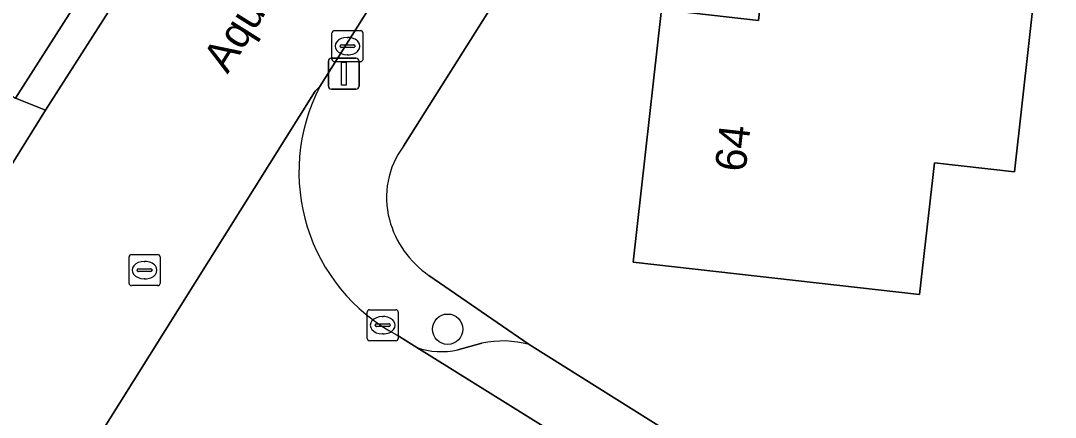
# Model space of a CAD drawing. Extents: x 162396 to 163643, y 386452 to 387406.
# Drawn here: x 162948.05 to 162981.44, y 387033.61 to 387046.39 of the extents above; entities that cross this region are included whole.
import ezdxf

# ---------------------------------------------------------------- set-up
doc = ezdxf.new("R2010")
doc.units = 0
for name, color, linetype in [('IMGEO_Boom', 7, 'Continuous'), ('IMGEO_Erf', 7, 'Continuous'), ('IMGEO_Groenvoorziening', 7, 'Continuous'), ('IMGEO_Kolk', 7, 'Continuous'), ('IMGEO_Lichtmast', 7, 'Continuous'), ('IMGEO_Openbare_ruimte_label', 7, 'Continuous'), ('IMGEO_Pand', 7, 'Continuous'), ('IMGEO_Pand_nummerreeks', 7, 'Continuous'), ('IMGEO_Parkeervlak_open', 7, 'Continuous'), ('IMGEO_Rijbaan_lokaal_open', 7, 'Continuous'), ('IMGEO_Rioolput', 7, 'Continuous'), ('IMGEO_Voetpad_open', 7, 'Continuous')]:
    doc.layers.add(name, color=color, linetype=linetype)

msp = doc.modelspace()

# ---------------------------------------------------------------- linework, layer by layer
at = {"layer": 'IMGEO_Boom'}
msp.add_circle((162961.83, 387036.448), 0.489, dxfattribs=at)
at = {"layer": 'IMGEO_Erf'}
for points in [[(162979.934, 387072.163), (162977.128, 387068.53), (162974.731, 387065.026), (162960.405, 387042.352)], [(162961.225, 387038.18), (162964.459, 387035.953), (162990.052, 387019.93), (162992.795, 387018.215), (163000, 387017.439), (163002.724, 387017.146), (163002.153, 387014.133), (163000, 387002.568), (162999.522, 387000), (162999.273, 386998.733), (162983.452, 386917.174), (162983.338, 386916.58), (162981.778, 386908.453)]]:
    msp.add_lwpolyline(points, dxfattribs=at)
msp.add_lwpolyline([(162980.122, 387041.524), (162977.543, 387041.815), (162977.063, 387037.568), (162967.816, 387038.612), (162968.734, 387046.749), (162971.862, 387046.396), (162972.389, 387051.073), (162981.089, 387050.091)], close=True, dxfattribs=at)
for centre, radius, start, end in [((162962.615, 387040.699), 2.76, 143.2137, 195.0422), ((162962.992, 387040.782), 3.145, 194.7138, 235.8186)]:
    msp.add_arc(centre, radius, start, end, dxfattribs=at)
at = {"layer": 'IMGEO_Groenvoorziening'}
msp.add_lwpolyline([(162964.245, 387069.484), (162941.168, 387071.891), (162939.105, 387055.217), (162936.596, 387055.509), (162935.833, 387055.438), (162935.116, 387055.166), (162934.413, 387053.638), (162934.581, 387052.537), (162935.398, 387051.666), (162947.885, 387043.899)], close=True, dxfattribs=at)
at = {"layer": 'IMGEO_Kolk'}
for p, q in [((162958.171, 387046.07), (162959.023, 387046.07)), ((162958.096, 387045.144), (162958.096, 387045.996)), ((162958.584, 387045.85), (162958.609, 387045.85)), ((162959.097, 387045.996), (162959.097, 387045.144)), ((162958.355, 387045.564), (162958.355, 387045.576)), ((162958.793, 387045.527), (162958.395, 387045.527)), ((162958.398, 387045.613), (162958.796, 387045.613)), ((162958.839, 387045.576), (162958.839, 387045.564)), ((162959.023, 387045.07), (162958.171, 387045.07)), ((162958.607, 387045.29), (162958.582, 387045.29)), ((162959.308, 387037.076), (162960.16, 387037.076)), ((162959.233, 387036.15), (162959.233, 387037.002)), ((162959.721, 387036.856), (162959.746, 387036.856)), ((162960.234, 387037.002), (162960.234, 387036.15)), ((162959.492, 387036.57), (162959.492, 387036.582)), ((162959.93, 387036.533), (162959.532, 387036.533)), ((162959.535, 387036.619), (162959.933, 387036.619)), ((162959.976, 387036.582), (162959.976, 387036.57)), ((162960.16, 387036.076), (162959.308, 387036.076)), ((162959.744, 387036.296), (162959.719, 387036.296))]:
    msp.add_line(p, q, dxfattribs=at)
for points in [[(162958.171, 387046.07), (162959.023, 387046.07)], [(162958.096, 387045.144), (162958.096, 387045.996)], [(162959.097, 387045.996), (162959.097, 387045.144)], [(162959.023, 387045.07), (162958.171, 387045.07)], [(162959.308, 387037.076), (162960.16, 387037.076)], [(162959.233, 387036.15), (162959.233, 387037.002)], [(162960.234, 387037.002), (162960.234, 387036.15)], [(162960.16, 387036.076), (162959.308, 387036.076)]]:
    msp.add_lwpolyline(points, dxfattribs=at)
for centre, radius, start, end in [((162958.173, 387045.994), 0.0765, 91.552, 178.448), ((162958.173, 387045.994), 0.0765, 91.552, 178.448), ((162959.021, 387045.994), 0.0765, 1.552, 88.448), ((162959.021, 387045.994), 0.0765, 1.552, 88.448), ((162958.395, 387045.573), 0.0403, 85.8775, 175.7526), ((162958.392, 387045.563), 0.0366, 178.938, 274.7102), ((162958.796, 387045.57), 0.043, 264.8664, 352.4533), ((162958.8, 387045.575), 0.0386, 1.7309, 96.639), ((162958.173, 387045.146), 0.0765, 181.552, 268.448), ((162958.173, 387045.146), 0.0765, 181.552, 268.448), ((162959.021, 387045.146), 0.0765, 271.552, 358.448), ((162959.021, 387045.146), 0.0765, 271.552, 358.448), ((162959.31, 387037), 0.0765, 91.552, 178.448), ((162959.31, 387037), 0.0765, 91.552, 178.448), ((162960.158, 387037), 0.0765, 1.552, 88.448), ((162960.158, 387037), 0.0765, 1.552, 88.448), ((162959.532, 387036.579), 0.0403, 85.8775, 175.7526), ((162959.529, 387036.569), 0.0366, 178.938, 274.7102), ((162959.933, 387036.576), 0.043, 264.8664, 352.4533), ((162959.937, 387036.581), 0.0386, 1.7309, 96.639), ((162959.31, 387036.152), 0.0765, 181.552, 268.448), ((162959.31, 387036.152), 0.0765, 181.552, 268.448), ((162960.158, 387036.152), 0.0765, 271.552, 358.448), ((162960.158, 387036.152), 0.0765, 271.552, 358.448)]:
    msp.add_arc(centre, radius, start, end, dxfattribs=at)
for centre, major_axis, ratio, start_param, end_param in [((162958.583, 387045.57), (-0.387, 0.002), 0.722429, 4.712389, 7.853982), ((162958.608, 387045.57), (-0.39, 0.002), 0.717154, 1.570796, 4.712389), ((162959.72, 387036.576), (-0.387, 0.002), 0.722429, 4.712389, 7.853982), ((162959.745, 387036.576), (-0.39, 0.002), 0.717154, 1.570796, 4.712389)]:
    msp.add_ellipse(centre, major_axis=major_axis, ratio=ratio, start_param=start_param, end_param=end_param, dxfattribs=at)
at = {"layer": 'IMGEO_Lichtmast'}
for p, q in [((162957.981, 387044.284), (162957.981, 387045.084)), ((162957.981, 387045.084), (162957.981, 387044.284)), ((162958.081, 387045.184), (162958.871, 387045.184)), ((162958.871, 387045.184), (162958.081, 387045.184)), ((162958.971, 387045.084), (162958.971, 387044.284)), ((162958.971, 387044.284), (162958.971, 387045.084)), ((162958.871, 387044.184), (162958.081, 387044.184)), ((162958.081, 387044.184), (162958.871, 387044.184))]:
    msp.add_line(p, q, dxfattribs=at)
msp.add_lwpolyline([(162958.401, 387045.059), (162958.551, 387045.059), (162958.551, 387044.309), (162958.401, 387044.309), (162958.401, 387045.059)], dxfattribs=at)
for centre, start, end in [((162958.081, 387045.084), 90, 180), ((162958.081, 387045.084), 90, 180), ((162958.871, 387045.084), 0, 90), ((162958.871, 387045.084), 360, 90), ((162958.081, 387044.284), 180, 270), ((162958.081, 387044.284), 180, 270), ((162958.871, 387044.284), 270, 0), ((162958.871, 387044.284), 270, 0)]:
    msp.add_arc(centre, 0.1, start, end, dxfattribs=at)
at = {"layer": 'IMGEO_Pand'}
msp.add_lwpolyline([(162977.543, 387041.815), (162980.122, 387041.524), (162981.089, 387050.091), (162972.389, 387051.073), (162971.862, 387046.396), (162968.734, 387046.749), (162967.816, 387038.612), (162977.063, 387037.568)], close=True, dxfattribs=at)
at = {"layer": 'IMGEO_Parkeervlak_open'}
for points in [[(162960.832, 387035.859), (162977.884, 387025.258), (162991.899, 387016.536)], [(162962.937, 387035.997), (162962.161, 387035.785)], [(162991.074, 387017.691), (162990.052, 387019.93), (162964.459, 387035.953)]]:
    msp.add_lwpolyline(points, dxfattribs=at)
for centre, radius, start, end in [((162963.609, 387032.908), 3.161, 74.4079, 102.2803), ((162961.626, 387038.149), 2.424, 250.8758, 282.7502)]:
    msp.add_arc(centre, radius, start, end, dxfattribs=at)
at = {"layer": 'IMGEO_Rijbaan_lokaal_open'}
for points in [[(162966.768, 387071.483), (162948.849, 387043.507), (162945.907, 387038.803), (162941.229, 387031.323), (162938.465, 387026.904), (162937.436, 387025.258), (162921.686, 387000.002), (162915.342, 386989.987), (162914.431, 386990.593), (162914.143, 386990.14), (162911.404, 386985.942), (162911.138, 386985.441), (162912.089, 386984.831), (162909.331, 386979.699), (162906.632, 386973.865), (162905.275, 386970.114), (162896.686, 386945.321)], [(162928.216, 387071.142), (162925.71, 387048.745), (162929.833, 387048.448), (162929.843, 387048.447), (162930.466, 387048.352), (162931.078, 387048.201), (162931.674, 387047.997), (162932.25, 387047.739), (162932.8, 387047.432), (162945.216, 387039.485), (162945.907, 387038.803), (162948.849, 387043.507), (162947.885, 387043.899)], [(162893.927, 386924.59), (162901.627, 386939.333), (162906.38, 386952.275), (162909.185, 386960.036), (162912.927, 386970.387), (162914.676, 386974.714), (162915.597, 386976.559), (162916.277, 386977.92), (162917.178, 386979.724), (162920.646, 386985.26), (162923.023, 386989.056), (162927.543, 386996.272), (162929.878, 387000), (162929.936, 387000.092), (162941.722, 387018.853), (162943.715, 387022.032), (162945.076, 387024.193), (162948.049, 387028.821), (162949.072, 387030.463), (162949.283, 387030.941), (162957.556, 387044.115), (162957.708, 387044.272), (162960.889, 387049.333)], [(162957.708, 387044.272), (162957.556, 387044.115), (162949.283, 387030.941), (162949.072, 387030.463)], [(162993.578, 387015.491), (162991.899, 387016.536), (162977.884, 387025.258), (162960.832, 387035.859), (162960.197, 387036.254)]]:
    msp.add_lwpolyline(points, dxfattribs=at)
msp.add_arc((162962.984, 387041.515), 5.953, 152.4074, 242.0841, dxfattribs=at)
at = {"layer": 'IMGEO_Rioolput'}
for p, q in [((162951.545, 387037.925), (162951.545, 387038.777)), ((162951.62, 387038.851), (162952.472, 387038.851)), ((162952.546, 387038.777), (162952.546, 387037.925)), ((162951.847, 387038.394), (162952.245, 387038.394)), ((162952.033, 387038.631), (162952.058, 387038.631)), ((162951.804, 387038.345), (162951.804, 387038.357)), ((162952.242, 387038.308), (162951.844, 387038.308)), ((162952.056, 387038.071), (162952.031, 387038.071)), ((162952.288, 387038.357), (162952.288, 387038.345)), ((162952.472, 387037.851), (162951.62, 387037.851))]:
    msp.add_line(p, q, dxfattribs=at)
for points in [[(162951.545, 387037.925), (162951.545, 387038.777)], [(162951.62, 387038.851), (162952.472, 387038.851)], [(162952.546, 387038.777), (162952.546, 387037.925)], [(162952.472, 387037.851), (162951.62, 387037.851)]]:
    msp.add_lwpolyline(points, dxfattribs=at)
for centre, radius, start, end in [((162951.622, 387038.775), 0.0765, 91.552, 178.448), ((162951.622, 387038.775), 0.0765, 91.552, 178.448), ((162952.47, 387038.775), 0.0765, 1.552, 88.448), ((162952.47, 387038.775), 0.0765, 1.552, 88.448), ((162951.844, 387038.354), 0.0403, 85.8775, 175.7526), ((162952.249, 387038.356), 0.0386, 1.7309, 96.639), ((162951.841, 387038.344), 0.0366, 178.938, 274.7102), ((162952.245, 387038.351), 0.043, 264.8664, 352.4533), ((162951.622, 387037.927), 0.0765, 181.552, 268.448), ((162951.622, 387037.927), 0.0765, 181.552, 268.448), ((162952.47, 387037.927), 0.0765, 271.552, 358.448), ((162952.47, 387037.927), 0.0765, 271.552, 358.448)]:
    msp.add_arc(centre, radius, start, end, dxfattribs=at)
for centre, major_axis, ratio, start_param, end_param in [((162952.032, 387038.351), (-0.387, 0.002), 0.722429, 4.712389, 7.853982), ((162952.057, 387038.351), (-0.39, 0.002), 0.717154, 1.570796, 4.712389)]:
    msp.add_ellipse(centre, major_axis=major_axis, ratio=ratio, start_param=start_param, end_param=end_param, dxfattribs=at)
at = {"layer": 'IMGEO_Voetpad_open'}
msp.add_lwpolyline([(162969.628, 387075.626), (162972.815, 387079.637), (162976.657, 387083.529), (162975.905, 387084.367), (162972.077, 387080.389), (162968.68, 387076.216), (162965.976, 387072.585), (162964.245, 387069.484), (162947.885, 387043.899), (162948.849, 387043.507), (162966.768, 387071.483)], close=True, dxfattribs=at)
for points in [[(162960.405, 387042.352), (162974.731, 387065.026), (162977.128, 387068.53), (162979.934, 387072.163)], [(162960.889, 387049.333), (162957.708, 387044.272)], [(162964.459, 387035.953), (162961.225, 387038.18)], [(162960.197, 387036.254), (162960.832, 387035.859)], [(162962.161, 387035.785), (162962.937, 387035.997)]]:
    msp.add_lwpolyline(points, dxfattribs=at)
for centre, radius, start, end in [((162962.984, 387041.515), 5.953, 152.4074, 242.0841), ((162962.615, 387040.699), 2.76, 143.2137, 195.0422), ((162962.992, 387040.782), 3.145, 194.7138, 235.8186), ((162963.609, 387032.908), 3.161, 74.4079, 102.2803), ((162961.626, 387038.149), 2.424, 250.8758, 282.7502)]:
    msp.add_arc(centre, radius, start, end, dxfattribs=at)

# ---------------------------------------------------------------- texts
at = {"layer": 'IMGEO_Openbare_ruimte_label'}
msp.add_text('Aquariuslaan', height=1, rotation=57.9946, dxfattribs=at).set_placement((162954.725, 387044.651))
at = {"layer": 'IMGEO_Pand_nummerreeks'}
msp.add_text('64', height=1, rotation=83.5632, dxfattribs=at).set_placement((162971.442, 387041.491))

doc.saveas('drawing.dxf')
